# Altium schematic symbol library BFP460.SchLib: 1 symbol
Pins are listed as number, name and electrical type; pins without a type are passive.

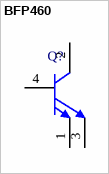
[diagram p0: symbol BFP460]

## BFP460
designator Q?
NPN Silicon RF Transistor, 4.5 V VCEO, 50 mA IC, 17.5 dB Gmax, SOT343, Green; Manufacturer: Infineon; PartNumber: BFP460; Gmax (typ): 17.5 dB; Green: yes; IC (max): 50 mA; NFmin (typ): 1.1 dB; Ptot (max): 200 mW; VCEO (max): 4.5 V
footprint INF-SOT343_V (SOT343, 4-Leads, Body 2x1.25 mm)
pins: 1 E, 2 C, 3 E, 4 B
